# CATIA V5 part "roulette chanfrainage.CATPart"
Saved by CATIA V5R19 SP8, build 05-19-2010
Part number: roulette chanfrainage
Bounding box of the stored display mesh (mm): x -2.5 to 2.5, y -4.999 to 4.999, z -4.999 to 4.999
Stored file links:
  G:\EU_thinkMotion\CFAO_2010\MMS_groupe3\MMS_groupe3\A reprendre\ftixier\florent-tixier\florent-tixier\roulette chanfrainage.CATPart
  C:\Users\Azote\Desktop\CFAO\coupe_tube1.CATProduct
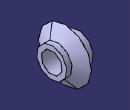
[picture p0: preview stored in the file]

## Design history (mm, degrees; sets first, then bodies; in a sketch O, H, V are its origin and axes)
External parameters (linked from other documents)
  External.R8 = 5 mm
Set1
  Sketch1 "roulette_chanfreinage", origin (0, 0, 0), H (0, 1, 0), V (0, 0, 1), geometry linked from another document
  Line1 "Axe_vis": linked copy from another document
  Point1 "Centre_roulette_chanfreinage": linked copy from another document
Body1 (main body)
  Point2 "Centre_roulette_chanfreinage": stored without definition
  Sketch2 on zx-plane, origin (0, 0, 0), H (-1, 0, 0), V (0, 0, 1)
    line L1 (-2.5, -2.8578) -> (-1.5, -2.8578)
    line L2 (-1.5, -2.8578) -> (0, -5)
    point P3 (0, -5)
    line L3 (0, -5) -> (1.5, -2.8578)
    point P4 (1.5, -2.8578)
    line L4 (1.5, -2.8578) -> (2.5, -2.8578)
    line L5 (2.5, -2.8578) -> (2.5, -2)
    line L6 (2.5, -2) -> (-2.5, -2)
    line L7 (-2.5, -2) -> (-2.5, -2.8578)
    reference projected point E1 (0, 0) from Point2
    angle L3 L2 = 70
    angle L3 V = 35
    length L4 = 1
    length L1 = 1
    length L6 = 5
    distance P3 E1 = 5 {= External.R8}
    distance L6 H = 2
    horizontal: L1 H, L4 H, L6 H
    coincidence: P3 V, P4 L1
    vertical: L5 V, L7 V
  Line2: type Angle, RefPoint Point1, Curve Line1, Support zx-plane, Start 0, End 20, Angle 90
  Shaft1: profile Sketch2, axis Line2, angle 360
